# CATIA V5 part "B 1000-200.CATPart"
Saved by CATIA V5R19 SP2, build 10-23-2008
Part number: B 1000-200
Bounding box of the stored display mesh (mm): x -24.865 to 24.865, y -24.997 to 24.997, z 0 to 495
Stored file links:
  C:\Users\Bora\Desktop\3D Katı model\B serisi\B 1000\B 1000-200.CATPart
  C:\Program Files\Dassault Systemes\B19\intel_a\reffiles\standard\MetricThickPitch.txt
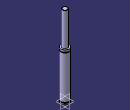
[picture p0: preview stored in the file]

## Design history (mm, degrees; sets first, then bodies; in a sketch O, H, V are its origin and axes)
Body1 (main body)
  Sketch1 on yz-plane, origin (0, 0, 0), H (0, 1, 0), V (0, 0, 1)
    point P1 (25, 279.5)
    point P2 (25, 275.5)
    point P3 (25, 279.5)
    point P6 (25, 275.5)
    point P9 (15, 494)
    point P11 (15, 494)
    arc A1 centre (25, 277.5) radius 2 from (25, 279.5) to (25, 275.5) ccw
    line L1 (25, 279.5) -> (25, 292)
    line L2 (25, 13) -> (25, 275.5)
    line L3 (21.5, 13) -> (21.5, 8)
    arc A2 centre (14, 494) radius 1 from (15, 494) to (14, 495) ccw
    line L4 (15, 494) -> (15, 292)
    line L5 (25, 0) -> (25, 8)
    line L6 (14, 495) -> (0, 495)
    point P15 (0, 495)
    line L7 (15, 292) -> (25, 292)
    line L8 (0, 0) -> (25, 0)
    line L9 (21.5, 13) -> (25, 13)
    line L10 (21.5, 8) -> (25, 8)
    coincidence: P15 V, P1 P3, P2 P6, P9 P11
    tangency: L6 A2
    horizontal: L7 H, L8 H, L9 H, L10 H
  Shaft1: profile Sketch1, axis Sketch1.V, angle 360
  Sketch2 on face of Shaft1 from Sketch1.L8, origin (0, 0, 0), H (1, 0, 0), V (0, -1, 0)
    point P1 (10, 0)
    distance P1 V = 10
  Hole1: placed by Sketch2, at (10, 0, 0) direction (0, 0, 1), diameter 6.647, depth 13, threaded "M8", thread diameter 8, thread depth 13, pitch 1.25
  CircPattern1: of Hole1, instances 2, angular step 180, axis from xy-plane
